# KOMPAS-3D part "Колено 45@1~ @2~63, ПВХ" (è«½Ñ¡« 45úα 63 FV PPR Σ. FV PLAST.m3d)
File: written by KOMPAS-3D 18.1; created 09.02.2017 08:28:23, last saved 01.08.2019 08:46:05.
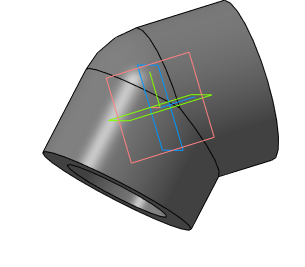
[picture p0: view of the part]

Document properties: Автор: Милов; Организация: Милов; Полное имя файла: D:\1 ПКИ 3D\Полипропиленовые фитинги, трубы\Колено 45гр 63 FV PPR ф. FV PLAST.m3d

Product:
- Part/product: Колено 45@1~ @2~63  | designation ПВХ
    Материал: Полипропилен  ГОСТ 26996-86 (density 900 kg/m3)
    Масса: 0.370628
    Раздел спецификации: Прочие изделия
- Part/product: Колено 45@1~ @2~63 FV PPR ф. "FV PLAST"
    Материал: Полипропилен  ГОСТ 26996-86 (density 900 kg/m3)
    Масса: 0.34448
    Раздел спецификации: Прочие изделия

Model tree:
1. Эскиз:1
2. Операция выдавливания:9
     Расстояние 1 = 44.5
3. Массив по концентрической сетке:1  (with: Операция выдавливания:9, Эскиз:1)  (2 pattern instances)
     Шаг 2 = 135
4. Эскиз:20  (with: Операция выдавливания:9)
5. Вырезать элемент выдавливания:6
     Расстояние 1 = 44.5
6. Эскиз:21  (with: Операция выдавливания:9)
7. Вырезать элемент выдавливания:7
     Расстояние 1 = 44.5
8. Эскиз:22  (with: Операция выдавливания:9)
9. Вырезать элемент выдавливания:8
     Расстояние 1 = 27.4
10. Массив по концентрической сетке:3  (with: Вырезать элемент выдавливания:8, Эскиз:22)  (2 pattern instances)
     Шаг 2 = 135
11. Эскиз:23  (with: Операция выдавливания:9, Вырезать элемент выдавливания:6)
12. Операция вращения:1  (labels: Полипропилен  ГОСТ 26996-86)
     Угол 1 = 45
